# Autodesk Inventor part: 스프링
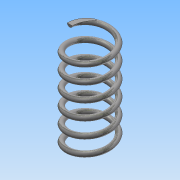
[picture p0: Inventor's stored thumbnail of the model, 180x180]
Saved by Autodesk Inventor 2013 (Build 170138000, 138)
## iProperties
Created: 2016-04
Part Number: 스프링
Material: 강철, 탄소
Document SubType Name: Modeling
Designer: Administrator
Density: 7.87 g/cm^3
Mass: 7.36979 g
Surface Area: 18.963 cm^2
Volume: 0.93644 cm^3
Author: Administrator
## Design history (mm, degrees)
sketch "스케치1"
  geometry: L1 (0, 0)-(8, 0); L2 (8, 37)-(0, 37); L3 (0, 37)-(0, 0); C1 r 1 at (8, 0)
  constraints: 6 end point, 2 parallel, 1 centre point, 1 coincident, 1 horizontal, 1 vertical
  dimensions: "d0" = 2 diameter of C1; "d1" = 16 diameter of L1.end L3; "d2" = 37 distance between parallel lines of L1 L2 (derived)
feature "코일1" sketch "스케치1" pitch "d3" = 10; turns "d5" = 6; dims "d4" = 37 (= d2), "d6" = 0, angle "d7" = 90 deg, angle "d8" = 90 deg, "d9" = 0, "d10" = 0
sketch "스케치2"
  geometry: L1 (-25.168, 0)-(25.168, 0); L2 (25.168, 0)-(25.168, 37); L3 (25.168, 37)-(-25.168, 37); L4 (-25.168, 37)-(-25.168, 0); 2 further points
  constraints: 8 end point, 2 parallel, 1 coincident, 1 horizontal, 1 midpoint, 1 perpendicular
  dimensions: "d11" = 37 distance between parallel lines of L1 L3 (derived); "d13" = 50.33575 distance between parallel lines of L2 L4
extrude "돌출1" sketch "스케치2" stored distance "d14" = 0; taper "d15" = 0 deg
node "솔리드1"
